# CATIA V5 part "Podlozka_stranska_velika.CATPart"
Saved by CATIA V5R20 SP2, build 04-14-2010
Part number: podloka_6mm
Bounding box of the stored display mesh (mm): x -5.91 to 5.91, y -5.992 to 5.992, z 0 to 3.3
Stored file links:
  C:\Documents and Settings\Administrator\My Documents\Hobi_dokumenti\CAD_CNC\Clap_CATIA\Podlozka_stranska_velika.CATPart
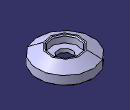
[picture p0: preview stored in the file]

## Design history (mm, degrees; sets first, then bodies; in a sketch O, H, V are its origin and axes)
StDynAnalysisRootNodeFeature1 "CATStDynAnalysisRootNodeName"
Set1
  Line1: type PtDir, RefPoint Sketch1.O, Direction Sketch1.V, Start 0, End 3
Body1 (main body)
  Sketch1 on yz-plane, origin (0, 0, 0), H (0, 1, 0), V (0, 0, 1)
    point P1 (-3, 0)
    line L1 (-3, 0) -> (-6, 0)
    line L2 (-3, 1) -> (-3, 0)
    point P3 (-3, 1)
    line L3 (-3, 1) -> (-1.6, 1)
    point P4 (-1.6, 1)
    line L4 (-1.6, 1) -> (-1.6, 1.8)
    point P5 (-1.6, 1.8)
    line L5 (-1.6, 1.8) -> (-3, 1.8)
    point P6 (-3, 1.8)
    line L6 (-3, 1.8) -> (-3, 3.3)
    point P7 (-3, 3.3)
    line L7 (-3, 3.3) -> (-3.5, 3.3)
    point P8 (-3.5, 3.3)
    reference intersected line E1 through (0, 0) direction (-1, 0) from xy-plane
    reference intersected line E3 through (0, 0) direction (0, 1) from zx-plane
    line L8 (-6, 0) -> (-6, 2)
    line L9 (-6, 2) -> (-3.5, 3.3)
    distance V L2 = 3
    distance P7 P8 = 0.5
    distance P4 P5 = 0.8
    distance P6 P7 = 1.5
    distance P5 P6 = 1.4
    distance P3 P1 = 1
    distance V L4 = 1.6
    length L8 = 2
    distance O L8 = 6
    coincidence: P1 H
    horizontal: L1 H, L3 H, L5 H, L7 H, E1 H
    vertical: L2 V, L4 V, L6 V, E3 V, L8 V
    perpendicularity: E1 L4
  Shaft1: profile Sketch1, axis Line1, angle 360
  Chamfer1: length 0.2, angle 45, on edge [face of Shaft1 from Sketch1.L2 | face of Shaft1 from Sketch1.L1]; edge [face of Shaft1 from Sketch1.L7 | face of Shaft1 from Sketch1.L6]; edge [face of Shaft1 from Sketch1.L1 | face of Shaft1 from Sketch1.L8]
